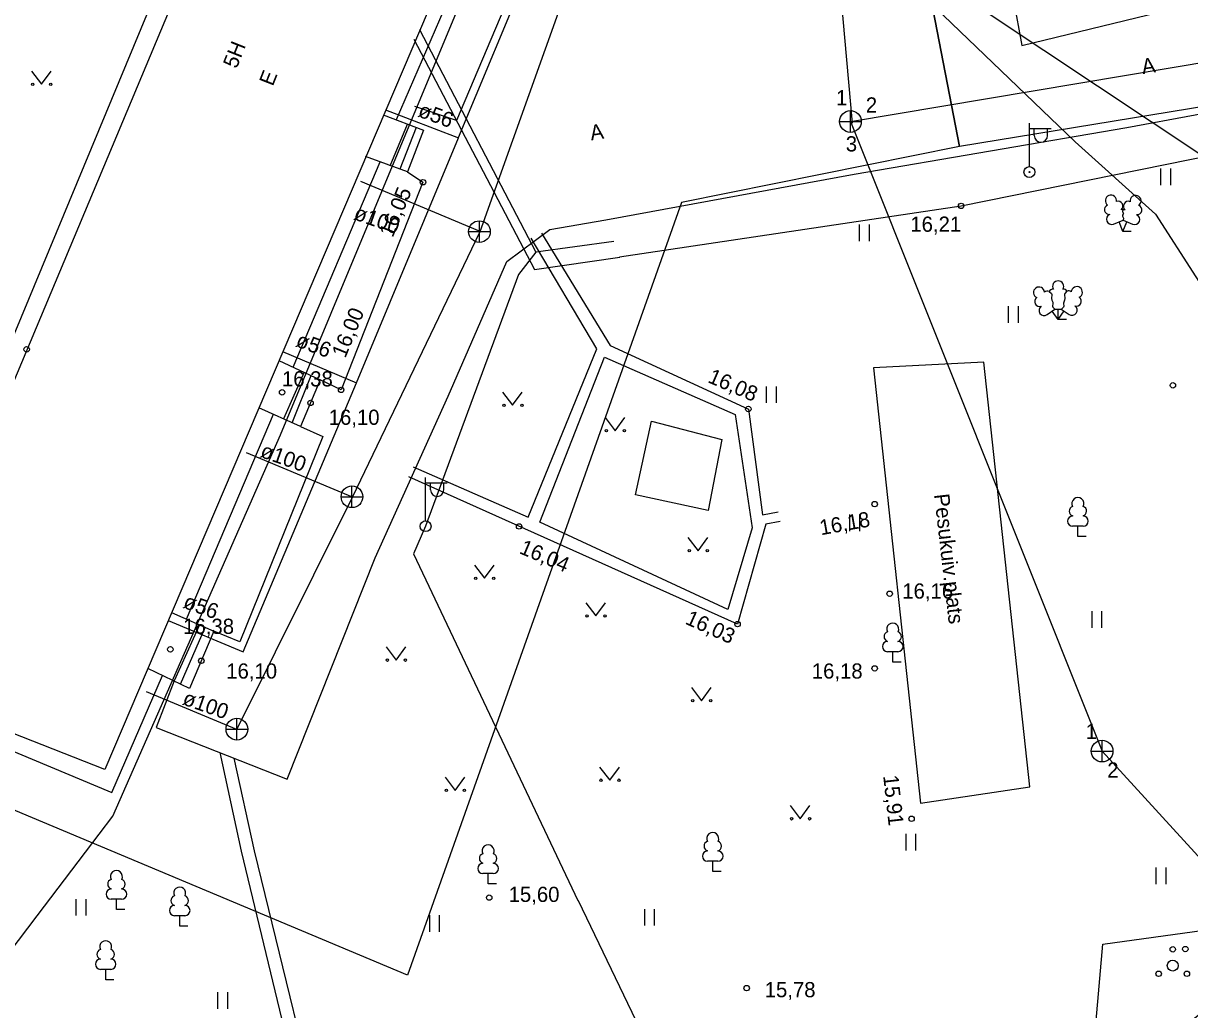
# Model space of a CAD drawing. Extents: x 713540 to 713867, y 6589774 to 6590061.
# Drawn here: x 713597.8 to 713651.5, y 6589826.2 to 6589871.6 of the extents above; entities that cross this region are included whole.
import ezdxf

# ---------------------------------------------------------------- set-up
doc = ezdxf.new("R2010")
doc.units = 0
for name, color, linetype in [('HALJASTUS', 7, 'Continuous'), ('HOONE', 7, 'Continuous'), ('HOONEDET', 7, 'Continuous'), ('KKAEV', 7, 'Continuous'), ('KORGUS', 7, 'Continuous'), ('KTRASS', 7, 'Continuous'), ('MPKAABEL', 7, 'Continuous'), ('POST', 7, 'Continuous'), ('PUU', 7, 'Continuous'), ('SITRASS', 7, 'Continuous'), ('TEE', 7, 'Continuous'), ('TORU NR', 7, 'Continuous'), ('Слой 1', 7, 'Continuous')]:
    doc.layers.add(name, color=color, linetype=linetype)

msp = doc.modelspace()

# ---------------------------------------------------------------- linework, layer by layer
at = {"layer": 'HALJASTUS'}
for p, q in [((713598.127, 6589869.437), (713598.59, 6589868.83)), ((713598.59, 6589868.83), (713599.036, 6589869.437)), ((713650.152, 6589864.949), (713650.152, 6589864.188)), ((713650.607, 6589864.949), (713650.607, 6589864.188)), ((713636.269, 6589862.366), (713636.269, 6589861.605)), ((713636.724, 6589862.366), (713636.724, 6589861.605)), ((713643.136, 6589858.602), (713643.136, 6589857.841)), ((713643.592, 6589858.602), (713643.592, 6589857.841)), ((713642.015, 6589856.033), (713636.926, 6589855.774)), ((713636.926, 6589855.774), (713639.084, 6589835.71)), ((713644.128, 6589836.46), (713642.015, 6589856.033)), ((713619.837, 6589854.647), (713620.3, 6589854.04)), ((713620.3, 6589854.04), (713620.746, 6589854.647)), ((713631.986, 6589854.911), (713631.986, 6589854.15)), ((713632.441, 6589854.911), (713632.441, 6589854.15)), ((713624.557, 6589853.477), (713625.02, 6589852.87)), ((713625.02, 6589852.87), (713625.466, 6589853.477)), ((713635.826, 6589849.007), (713635.826, 6589848.246)), ((713636.281, 6589849.007), (713636.281, 6589848.246)), ((713628.377, 6589847.947), (713628.84, 6589847.34)), ((713628.84, 6589847.34), (713629.286, 6589847.947)), ((713618.537, 6589846.677), (713619, 6589846.07)), ((713619, 6589846.07), (713619.446, 6589846.677)), ((713623.667, 6589844.947), (713624.13, 6589844.34)), ((713624.13, 6589844.34), (713624.576, 6589844.947)), ((713646.977, 6589844.552), (713646.977, 6589843.791)), ((713647.432, 6589844.552), (713647.432, 6589843.791)), ((713614.467, 6589842.907), (713614.93, 6589842.3)), ((713614.93, 6589842.3), (713615.376, 6589842.907)), ((713628.537, 6589841.037), (713629, 6589840.43)), ((713629, 6589840.43), (713629.446, 6589841.037)), ((713624.307, 6589837.377), (713624.77, 6589836.77)), ((713624.77, 6589836.77), (713625.216, 6589837.377)), ((713617.187, 6589836.907), (713617.65, 6589836.3)), ((713617.65, 6589836.3), (713618.096, 6589836.907)), ((713639.084, 6589835.71), (713644.128, 6589836.46)), ((713633.087, 6589835.597), (713633.55, 6589834.99)), ((713633.55, 6589834.99), (713633.996, 6589835.597)), ((713638.41, 6589834.293), (713638.41, 6589833.532)), ((713638.865, 6589834.293), (713638.865, 6589833.532)), ((713649.93, 6589832.743), (713649.93, 6589831.982)), ((713650.385, 6589832.743), (713650.385, 6589831.982)), ((713600.178, 6589831.292), (713600.178, 6589830.531)), ((713600.633, 6589831.292), (713600.633, 6589830.531)), ((713616.462, 6589830.549), (713616.462, 6589829.788)), ((713616.917, 6589830.549), (713616.917, 6589829.788)), ((713626.371, 6589830.835), (713626.371, 6589830.074)), ((713626.826, 6589830.835), (713626.826, 6589830.074)), ((713606.708, 6589826.998), (713606.708, 6589826.237)), ((713607.163, 6589826.998), (713607.163, 6589826.237))]:
    msp.add_line(p, q, dxfattribs=at)
msp.add_lwpolyline([(713652.155, 6589829.862), (713652.122, 6589826.127), (713646.843, 6589821.832), (713647.493, 6589829.212), (713652.155, 6589829.862)], dxfattribs=at)
for centre, radius in [((713598.189, 6589868.83), 0.055), ((713599.018, 6589868.83), 0.055), ((713619.899, 6589854.04), 0.055), ((713620.728, 6589854.04), 0.055), ((713624.619, 6589852.87), 0.055), ((713625.448, 6589852.87), 0.055), ((713628.439, 6589847.34), 0.055), ((713629.268, 6589847.34), 0.055), ((713618.599, 6589846.07), 0.055), ((713619.428, 6589846.07), 0.055), ((713623.729, 6589844.34), 0.055), ((713624.558, 6589844.34), 0.055), ((713614.529, 6589842.3), 0.055), ((713615.358, 6589842.3), 0.055), ((713628.599, 6589840.43), 0.055), ((713629.428, 6589840.43), 0.055), ((713624.369, 6589836.77), 0.055), ((713625.198, 6589836.77), 0.055), ((713617.249, 6589836.3), 0.055), ((713618.078, 6589836.3), 0.055), ((713633.149, 6589834.99), 0.055), ((713633.978, 6589834.99), 0.055), ((713650.711, 6589828.975), 0.125), ((713650.711, 6589828.225), 0.25), ((713650.061, 6589827.85), 0.125), ((713651.361, 6589827.85), 0.125)]:
    msp.add_circle(centre, radius, dxfattribs=at)
at = {"layer": 'HOONE'}
for points in [[(713591.47, 6589841.21), (713616.703, 6589901.396), (713627, 6589897.096), (713601.51, 6589837.26), (713591.47, 6589841.21)], [(713613.11, 6589855.07), (713617.81, 6589866.37), (713617.81, 6589866.38), (713621.135, 6589874.38), (713622.75, 6589878.27), (713627.6, 6589890.2), (713629.907, 6589896.003)], [(713589.21, 6589818.4), (713598.395, 6589830.514), (713600.619, 6589833.447), (713601.88, 6589835.11), (713609.6, 6589852.68), (713621.203, 6589880.532)], [(713614.44, 6589867.65), (713617.81, 6589866.37)], [(713609.7, 6589856.52), (713613.11, 6589855.07)], [(713604.43, 6589844.13), (713607.89, 6589842.68), (713613.11, 6589855.07)]]:
    msp.add_lwpolyline(points, dxfattribs=at)
at = {"layer": 'HOONEDET'}
for points in [[(713625.586, 6589891.712), (713627.642, 6589896.627), (713627.941, 6589897.526), (713616.075, 6589902.488), (713590.52, 6589840.94), (713601.84, 6589836.21), (713604.17, 6589841.59)], [(713618.921, 6589876.423), (713614.93, 6589867.19)], [(713614.34, 6589867.42), (713616.19, 6589866.71)], [(713614.65, 6589865.08), (713615.45, 6589866.99)], [(713615.85, 6589866.84), (713615.1, 6589864.92)], [(713616.19, 6589866.71), (713615.45, 6589864.79)], [(713615.45, 6589864.79), (713613.52, 6589865.5)], [(713610.19, 6589855.8), (713614.19, 6589865.25)], [(713609.53, 6589856.11), (713611.44, 6589855.21)], [(713610.69, 6589855.57), (713609.75, 6589853.42)], [(713610.14, 6589853.24), (713611.02, 6589855.41)], [(713611.44, 6589855.21), (713610.53, 6589853.07)], [(713605.27, 6589844.19), (713609.28, 6589853.63)], [(713610.53, 6589853.07), (713608.6, 6589853.93)], [(713604.59, 6589844.49), (713606.54, 6589843.63)], [(713605.87, 6589843.93), (713604.7, 6589841.34)], [(713605, 6589841.2), (713606.13, 6589843.81)], [(713606.54, 6589843.63), (713605.42, 6589841)], [(713605.42, 6589841), (713603.49, 6589841.91)]]:
    msp.add_lwpolyline(points, dxfattribs=at)
at = {"layer": 'KKAEV'}
for p, q in [((713635.861, 6589866.616), (713635.861, 6589867.616)), ((713635.361, 6589867.116), (713636.361, 6589867.116)), ((713618.272, 6589862.041), (713619.272, 6589862.041)), ((713618.772, 6589861.541), (713618.772, 6589862.541)), ((713612.899, 6589849.328), (713612.899, 6589850.328)), ((713612.399, 6589849.828), (713613.399, 6589849.828)), ((713607.595, 6589838.62), (713607.595, 6589839.62)), ((713607.095, 6589839.12), (713608.095, 6589839.12)), ((713647.455, 6589837.608), (713647.455, 6589838.608)), ((713646.955, 6589838.108), (713647.955, 6589838.108))]:
    msp.add_line(p, q, dxfattribs=at)
for centre in [(713635.861, 6589867.116), (713618.772, 6589862.041), (713612.899, 6589849.828), (713607.595, 6589839.12), (713647.455, 6589838.108)]:
    msp.add_circle(centre, 0.5, dxfattribs=at)
at = {"layer": 'KORGUS'}
for centre in [(713616.17, 6589864.32), (713640.96, 6589863.23), (713597.91, 6589856.62), (713650.72, 6589854.96), (713609.68, 6589854.64), (713612.4, 6589854.75), (713610.99, 6589854.15), (713631.16, 6589853.87), (713636.98, 6589849.49), (713620.6, 6589848.46), (713637.67, 6589845.36), (713630.66, 6589843.96), (713604.53, 6589842.8), (713605.96, 6589842.27), (713636.98, 6589841.92), (713638.68, 6589834.99), (713619.22, 6589831.36), (713651.29, 6589828.99), (713631.08, 6589827.19)]:
    msp.add_circle(centre, 0.125, dxfattribs=at)
at = {"layer": 'KTRASS'}
for p, q in [((713635.861, 6589867.116), (713673.346, 6589873.423)), ((713635.861, 6589867.116), (713647.455, 6589838.108)), ((713647.455, 6589838.108), (713679.09, 6589803.497))]:
    msp.add_line(p, q, dxfattribs=at)
for points in [[(713633.446, 6589895.028), (713635.943, 6589867.043)], [(713618.805, 6589862.047), (713623.321, 6589874.689)], [(713618.805, 6589862.047), (713613.311, 6589864.352)], [(713612.924, 6589849.802), (713618.805, 6589862.047)], [(713612.924, 6589849.802), (713608.037, 6589851.852)], [(713607.591, 6589839.1), (713612.924, 6589849.802)], [(713607.591, 6589839.1), (713603.434, 6589840.844)]]:
    msp.add_lwpolyline(points, dxfattribs=at)
at = {"layer": 'MPKAABEL'}
for points in [[(713621.405, 6589921.156), (713617.009, 6589909.766), (713616.379, 6589906.228), (713617.893, 6589905.104), (713618.264, 6589904.829), (713628.654, 6589899.391), (713631.248, 6589897.024), (713632.991, 6589885.086), (713637.163, 6589875.703), (713640.145, 6589871.993), (713646.211, 6589866.173), (713649.924, 6589862.847), (713657.342, 6589851.294), (713662.171, 6589845.836), (713664.179, 6589844.049)], [(713616.01, 6589871.35), (713621.37, 6589861.09)], [(713624.963, 6589861.589), (713621.37, 6589861.09)], [(713621.37, 6589861.09), (713620.57, 6589860.06), (713616.29, 6589848.47)], [(713616.29, 6589848.47), (713615.73, 6589847.2), (713623.305, 6589831.225), (713623.323, 6589831.228), (713633.563, 6589809.916), (713632.313, 6589808.683), (713632.06, 6589808.423), (713623.36, 6589799.85), (713605.22, 6589798.05)]]:
    msp.add_lwpolyline(points, dxfattribs=at)
at = {"layer": 'POST'}
for p, q in [((713644.106, 6589865.036), (713644.106, 6589867.036)), ((713644.106, 6589866.786), (713645.106, 6589866.786)), ((713644.333, 6589866.465), (713644.333, 6589866.786)), ((713644.946, 6589866.465), (713644.946, 6589866.786)), ((713616.29, 6589848.72), (713616.29, 6589850.72)), ((713616.29, 6589850.47), (713617.29, 6589850.47)), ((713616.517, 6589850.149), (713616.517, 6589850.47)), ((713617.129, 6589850.149), (713617.129, 6589850.47))]:
    msp.add_line(p, q, dxfattribs=at)
for centre, radius in [((713644.106, 6589864.786), 0.25), ((713644.106, 6589864.786), 0.0234), ((713616.29, 6589848.47), 0.25)]:
    msp.add_circle(centre, radius, dxfattribs=at)
for centre in [(713644.639, 6589866.465), (713616.823, 6589850.149)]:
    msp.add_arc(centre, 0.306, 180, 0, dxfattribs=at)
at = {"layer": 'PUU'}
for p, q in [((713647.978, 6589862.389), (713648.423, 6589862.564)), ((713648.418, 6589862.054), (713648.243, 6589862.494)), ((713648.418, 6589862.054), (713648.598, 6589862.494)), ((713648.798, 6589862.054), (713648.418, 6589862.054)), ((713648.423, 6589862.564), (713648.863, 6589862.384)), ((713644.922, 6589858.219), (713645.282, 6589858.474)), ((713645.432, 6589857.999), (713645.157, 6589858.384)), ((713645.282, 6589858.474), (713645.577, 6589858.474)), ((713645.432, 6589857.999), (713645.432, 6589858.474)), ((713645.432, 6589857.999), (713645.702, 6589858.389)), ((713645.577, 6589858.474), (713645.937, 6589858.229)), ((713645.812, 6589857.999), (713645.432, 6589857.999)), ((713646.58, 6589848.466), (713646.1, 6589848.466)), ((713646.34, 6589847.991), (713646.34, 6589848.466)), ((713646.72, 6589847.991), (713646.34, 6589847.991)), ((713638.052, 6589842.689), (713637.572, 6589842.689)), ((713637.812, 6589842.214), (713637.812, 6589842.689)), ((713638.192, 6589842.214), (713637.812, 6589842.214)), ((713629.76, 6589833.035), (713629.28, 6589833.035)), ((713629.52, 6589832.56), (713629.52, 6589833.035)), ((713629.9, 6589832.56), (713629.52, 6589832.56)), ((713619.41, 6589832.465), (713618.93, 6589832.465)), ((713619.17, 6589831.99), (713619.17, 6589832.465)), ((713619.55, 6589831.99), (713619.17, 6589831.99)), ((713602.286, 6589831.284), (713601.806, 6589831.284)), ((713602.046, 6589830.809), (713602.046, 6589831.284)), ((713602.426, 6589830.809), (713602.046, 6589830.809)), ((713605.201, 6589830.525), (713604.721, 6589830.525)), ((713604.961, 6589830.05), (713604.961, 6589830.525)), ((713605.341, 6589830.05), (713604.961, 6589830.05)), ((713601.791, 6589828.052), (713601.311, 6589828.052)), ((713601.551, 6589827.577), (713601.551, 6589828.052)), ((713601.931, 6589827.577), (713601.551, 6589827.577))]:
    msp.add_line(p, q, dxfattribs=at)
for points in [[(713648.423, 6589863.059), (713648.403, 6589862.984), (713648.403, 6589862.964), (713648.413, 6589862.934), (713648.433, 6589862.899), (713648.438, 6589862.879), (713648.423, 6589862.844), (713648.398, 6589862.794), (713648.393, 6589862.769), (713648.398, 6589862.754), (713648.408, 6589862.724), (713648.443, 6589862.664), (713648.448, 6589862.644), (713648.443, 6589862.624), (713648.428, 6589862.589), (713648.423, 6589862.564)], [(713645.02, 6589859.286), (713645.122, 6589859.184), (713645.137, 6589859.154), (713645.137, 6589859.099), (713645.122, 6589859.009), (713645.122, 6589858.964), (713645.142, 6589858.884), (713645.182, 6589858.794), (713645.192, 6589858.749), (713645.187, 6589858.704), (713645.172, 6589858.639), (713645.172, 6589858.609), (713645.192, 6589858.569), (713645.217, 6589858.539), (713645.282, 6589858.474)], [(713645.836, 6589859.3), (713645.742, 6589859.184), (713645.727, 6589859.154), (713645.727, 6589859.099), (713645.742, 6589859.009), (713645.747, 6589858.964), (713645.727, 6589858.884), (713645.687, 6589858.794), (713645.677, 6589858.749), (713645.682, 6589858.704), (713645.697, 6589858.639), (713645.697, 6589858.609), (713645.677, 6589858.569), (713645.652, 6589858.539), (713645.582, 6589858.474)]]:
    msp.add_lwpolyline(points, dxfattribs=at)
for centre, radius, start, end in [((713647.861, 6589863.468), 0.256, 111.5027, 232.5173), ((713647.861, 6589863.468), 0.256, 350.4856, 111.5002), ((713648.997, 6589863.459), 0.256, 67.6168, 188.6314), ((713648.997, 6589863.459), 0.256, 306.5997, 67.6143), ((713647.787, 6589863.056), 0.224, 111.4304, 274.4987), ((713648.196, 6589863.217), 0.224, 308.5041, 111.5725), ((713648.659, 6589863.213), 0.225, 67.7016, 230.5126), ((713649.064, 6589863.047), 0.224, 264.6183, 67.6866), ((713647.892, 6589862.612), 0.237, 111.5014, 291.5004), ((713648.422, 6589862.821), 0.237, 66.7655, 111.5015), ((713648.953, 6589862.604), 0.237, 247.6166, 67.6155), ((713644.549, 6589859.236), 0.256, 125.5389, 246.5536), ((713644.549, 6589859.236), 0.256, 4.5218, 125.5364), ((713645.195, 6589859.186), 0.202, 84.7965, 150.2995), ((713645.432, 6589859.519), 0.256, 90.0013, 211.0159), ((713645.432, 6589859.519), 0.256, 328.9841, 89.9987), ((713645.67, 6589859.186), 0.202, 34.3857, 95.2035), ((713646.293, 6589859.252), 0.256, 55.522, 176.5367), ((713646.293, 6589859.252), 0.256, 294.5049, 55.5195), ((713644.577, 6589858.818), 0.224, 125.4667, 288.5349), ((713644.935, 6589859.103), 0.202, 65.2382, 130.7412), ((713645.909, 6589859.112), 0.202, 50.3173, 111.1351), ((713646.272, 6589858.834), 0.224, 252.5235, 55.5918), ((713644.786, 6589858.413), 0.237, 125.5377, 305.5366), ((713646.071, 6589858.425), 0.237, 235.5219, 55.5208), ((713646.34, 6589849.511), 0.277, 332.5799, 207.4201), ((713646.17, 6589849.164), 0.233, 109.0217, 253.1415), ((713646.51, 6589849.164), 0.233, 286.8508, 70.9859), ((713646.103, 6589848.704), 0.238, 90.0016, 269.3953), ((713646.578, 6589848.704), 0.238, 270.6047, 89.9984), ((713637.812, 6589843.734), 0.277, 332.5799, 207.4201), ((713637.642, 6589843.386), 0.233, 109.0217, 253.1415), ((713637.982, 6589843.386), 0.233, 286.8508, 70.9859), ((713637.575, 6589842.926), 0.238, 90.0016, 269.3953), ((713638.05, 6589842.926), 0.238, 270.6047, 89.9984), ((713629.52, 6589834.08), 0.277, 332.5799, 207.4201), ((713619.17, 6589833.51), 0.277, 332.5799, 207.4201), ((713629.35, 6589833.733), 0.233, 109.0217, 253.1415), ((713629.69, 6589833.733), 0.233, 286.8508, 70.9859), ((713619, 6589833.163), 0.233, 109.0217, 253.1415), ((713619.34, 6589833.163), 0.233, 286.8508, 70.9859), ((713629.283, 6589833.272), 0.238, 90.0016, 269.3953), ((713629.757, 6589833.272), 0.238, 270.6047, 89.9984), ((713602.046, 6589832.329), 0.277, 332.5799, 207.4201), ((713618.933, 6589832.702), 0.238, 90.0016, 269.3953), ((713619.407, 6589832.702), 0.238, 270.6047, 89.9984), ((713601.876, 6589831.981), 0.233, 109.0217, 253.1415), ((713602.217, 6589831.981), 0.233, 286.8508, 70.9859), ((713601.809, 6589831.521), 0.238, 90.0016, 269.3953), ((713602.284, 6589831.521), 0.238, 270.6047, 89.9984), ((713604.791, 6589831.223), 0.233, 109.0217, 253.1415), ((713604.961, 6589831.57), 0.277, 332.5799, 207.4201), ((713605.131, 6589831.223), 0.233, 286.8508, 70.9859), ((713604.723, 6589830.763), 0.238, 90.0016, 269.3953), ((713605.198, 6589830.763), 0.238, 270.6047, 89.9984), ((713601.551, 6589829.097), 0.277, 332.5799, 207.4201), ((713601.381, 6589828.75), 0.233, 109.0217, 253.1415), ((713601.721, 6589828.75), 0.233, 286.8508, 70.9859), ((713601.313, 6589828.29), 0.238, 90.0016, 269.3953), ((713601.788, 6589828.29), 0.238, 270.6047, 89.9984)]:
    msp.add_arc(centre, radius, start, end, dxfattribs=at)
at = {"layer": 'SITRASS'}
for points in [[(713622.526, 6589942.802), (713625.02, 6589914.21), (713630.01, 6589903.07), (713639.36, 6589886.76), (713642.3, 6589872.04), (713652.19, 6589865.47), (713653.052, 6589864.917), (713657.52, 6589862.05), (713661.076, 6589847.8), (713664.28, 6589834.96), (713666.33, 6589831.93), (713670.966, 6589832.394), (713671.39, 6589832.436), (713687.742, 6589834.073), (713694.81, 6589834.78), (713711.155, 6589837.134), (713711.376, 6589837.166), (713715.85, 6589837.81)], [(713615.75, 6589870.91), (713621.3, 6589860.3), (713625.233, 6589860.869), (713625.227, 6589860.885), (713640.96, 6589863.23), (713652.708, 6589865.606), (713653.172, 6589865.67), (713666.653, 6589868.422), (713666.793, 6589868.454), (713693.51, 6589873.89), (713696.19, 6589872.18), (713705.63, 6589819.79), (713706.98, 6589814.25), (713714.585, 6589815.353), (713715.248, 6589815.449), (713720.22, 6589816.17), (713721.73, 6589808.13), (713722.95, 6589800.79), (713723.002, 6589800.484), (713723.148, 6589799.687), (713725.92, 6589783.295)]]:
    msp.add_lwpolyline(points, dxfattribs=at)
at = {"layer": 'TEE'}
for points in [[(713620.883, 6589876.927), (713621.688, 6589876.558), (713617.719, 6589867.155), (713615.791, 6589867.804)], [(713643.373, 6589872.699), (713643.752, 6589870.615), (713650.078, 6589872.152), (713649.603, 6589874.03)], [(713604.7, 6589841.34), (713603.88, 6589839.2), (713609.91, 6589836.82), (713613.97, 6589847.02), (713617.324, 6589854.463), (713620.034, 6589860.662), (713622.012, 6589862.139), (713624.588, 6589862.589), (713636.035, 6589864.696), (713648.598, 6589866.836), (713651.744, 6589867.418), (713666.405, 6589870.131), (713667.395, 6589870.314), (713668.241, 6589865.803), (713669.69, 6589856.43), (713672.05, 6589851.73), (713677.154, 6589840.312), (713677.401, 6589839.977), (713681.17, 6589837.189), (713694.749, 6589839.642)], [(713648.598, 6589866.836), (713651.744, 6589867.418), (713666.405, 6589870.131), (713667.395, 6589870.314), (713668.241, 6589865.803), (713669.69, 6589856.43), (713672.05, 6589851.73), (713677.154, 6589840.312), (713677.401, 6589839.977), (713681.17, 6589837.189), (713694.749, 6589839.642)], [(713615.45, 6589864.79), (713616.17, 6589864.32), (713612.4, 6589854.75), (713611.44, 6589855.21)], [(713615.71, 6589851.21), (713621.02, 6589848.89), (713624.18, 6589856.65), (713621.15, 6589861.74)], [(713621.63, 6589861.97), (713624.8, 6589856.8), (713631.16, 6589853.87), (713631.81, 6589848.99), (713632.537, 6589849.133)], [(713631.33, 6589848.4), (713630.21, 6589844.64), (713621.55, 6589848.65), (713624.53, 6589856.26)], [(713624.53, 6589856.26), (713630.55, 6589853.62), (713631.33, 6589848.4)], [(713610.53, 6589853.07), (713611.56, 6589852.61), (713607.73, 6589843.15), (713606.54, 6589843.63)], [(713629.93, 6589852.47), (713629.31, 6589849.2), (713625.96, 6589849.92), (713626.7, 6589853.31)], [(713626.7, 6589853.31), (713629.93, 6589852.47)], [(713632.626, 6589848.683), (713631.96, 6589848.56), (713630.66, 6589843.96), (713615.51, 6589850.74)], [(713606.81, 6589838.05), (713607.798, 6589833.497), (713611.421, 6589818.465), (713615.183, 6589802.779)], [(713607.45, 6589837.79), (713608.387, 6589833.509), (713612.008, 6589818.746), (713615.627, 6589803.656)]]:
    msp.add_lwpolyline(points, dxfattribs=at)
at = {"layer": 'Слой 1'}
for points in [[(713682.51, 6589917.77), (713690.33, 6589877.18), (713657.78, 6589870.72), (713657.67, 6589868.71), (713640.88, 6589865.96), (713635.67, 6589892.95), (713631.47, 6589895.07), (713633.95, 6589902.38), (713645.78, 6589933.24)], [(713577.92, 6589843.53), (713607.67, 6589912.62), (713633.95, 6589902.38), (713631.47, 6589895.07), (713635.67, 6589892.95), (713640.88, 6589865.96), (713628.08, 6589863.38), (713615.46, 6589827.79)]]:
    msp.add_lwpolyline(points, close=True, dxfattribs=at)

# ---------------------------------------------------------------- texts
at = {"layer": 'HALJASTUS'}
msp.add_text('Pesukuiv.plats', height=0.7, rotation=276.5368, dxfattribs=at).set_placement((713639.714, 6589849.932))
at = {"layer": 'HOONE'}
for s, p in [('5H', (713607.583, 6589869.516)), ('E', (713609.25, 6589868.709))]:
    msp.add_text(s, height=0.7, rotation=68.387, dxfattribs=at).set_placement(p)
at = {"layer": 'KORGUS'}
for s, rotation, p in [('16,05', 67.7116, (713614.773, 6589861.739)), ('16,00', 67.7116, (713612.59, 6589856.184)), ('16,08', 336.7255, (713629.248, 6589855.117)), ('16,18', 10.1718, (713634.505, 6589848.053)), ('16,04', 337.1336, (713620.565, 6589847.238)), ('16,03', 335.8052, (713628.206, 6589843.991)), ('15,91', 276.2635, (713637.37, 6589836.972))]:
    msp.add_text(s, height=0.7, rotation=rotation, dxfattribs=at).set_placement(p)
for s, p in [('16,21', (713638.622, 6589862.035)), ('16,38', (713609.672, 6589854.91)), ('16,10', (713611.825, 6589853.14)), ('16,16', (713638.25, 6589845.135)), ('16,38', (713605.122, 6589843.51)), ('16,10', (713607.105, 6589841.45)), ('16,18', (713634.082, 6589841.45)), ('15,60', (713620.115, 6589831.16)), ('15,78', (713631.912, 6589826.77))]:
    msp.add_text(s, height=0.7, dxfattribs=at).set_placement(p)
at = {"layer": 'TEE'}
for rotation, p in [(8.4572, (713649.331, 6589869.297)), (8.5254, (713623.917, 6589866.244))]:
    msp.add_text('A', height=0.7, rotation=rotation, dxfattribs=at).set_placement(p)
at = {"layer": 'TORU NR'}
for s, p in [('1', (713635.198, 6589867.86)), ('2', (713636.571, 6589867.528)), ('3', (713635.648, 6589865.736)), ('1', (713646.698, 6589838.67)), ('2', (713647.695, 6589836.89))]:
    msp.add_text(s, height=0.7, dxfattribs=at).set_placement(p)
for s, rotation, p in [('ø56', 339.8483, (713615.891, 6589867.362)), ('ø100', 340.4975, (713612.933, 6589862.625)), ('ø56', 339.8483, (713610.261, 6589856.772)), ('ø100', 340.4975, (713608.623, 6589851.675)), ('ø56', 339.8483, (713605.071, 6589844.732)), ('ø100', 340.4975, (713605.043, 6589840.275))]:
    msp.add_text(s, height=0.7, rotation=rotation, dxfattribs=at).set_placement(p)

doc.saveas('drawing.dxf')
